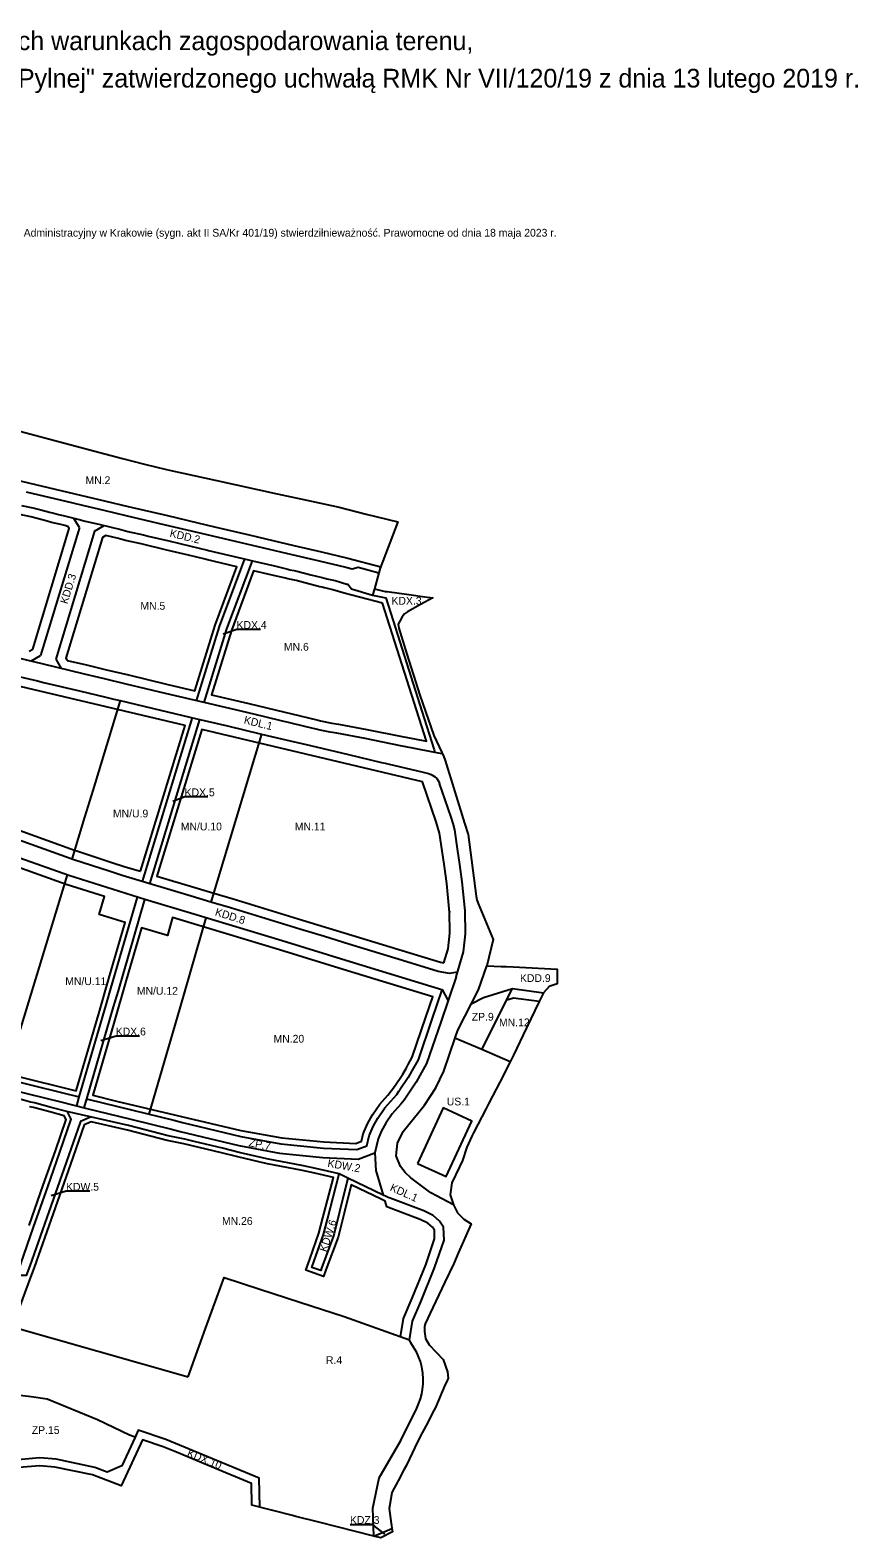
# Model space of a CAD drawing. Extents: x 7416945 to 7418410, y 5548550 to 5549803.
# Drawn here: x 7417879 to 7418410, y 5548834 to 5549803 of the extents above; entities that cross this region are included whole.
import ezdxf

# ---------------------------------------------------------------- set-up
doc = ezdxf.new("R2010")
doc.units = 0
for name, color, linetype in [('_LEGENDA_opisy', 7, 'Continuous'), ('info', 7, 'Continuous'), ('linie rozgraniczające', 7, 'Continuous'), ('nieprzekraczalna linia lokalizacyjna', 7, 'Continuous'), ('nieprzekraczalne linie zabudowy', 7, 'Continuous'), ('przeznaczenia terenów', 7, 'Continuous')]:
    doc.layers.add(name, color=color, linetype=linetype)

msp = doc.modelspace()

# ---------------------------------------------------------------- linework, layer by layer
at = {"layer": 'linie rozgraniczające'}
for p, q in [((7417910.44, 5549483.41), (7417907, 5549489.23)), ((7417920.17, 5549481.02), (7417926.47, 5549484.62)), ((7417879.25, 5549397.45), (7417885.56, 5549401.1)), ((7417895.3, 5549398.77), (7417898.72, 5549392.79)), ((7417983, 5549361.21), (7417950.85, 5549255.91)), ((7417955.64, 5549254.5), (7417987.87, 5549360.06)), ((7418027.45, 5549350.69), (7417994.99, 5549242.64)), ((7418166.75, 5549186.31), (7418172.2, 5549201.75)), ((7417864.45, 5548970.75), (7417980.26, 5548937.76)), ((7418099.66, 5548835.41), (7418111.24, 5548840.24))]:
    msp.add_line(p, q, dxfattribs=at)
for points in [[(7417852.72, 5549550.37), (7417888.31, 5549540.93), (7417919.44, 5549532.68), (7417938.2, 5549527.7), (7417952.33, 5549523.95), (7417966.49, 5549520.7), (7417974.19, 5549518.93), (7417977.16, 5549518.25), (7417997.67, 5549513.78), (7418037.57, 5549505.08), (7418059.54, 5549500.29), (7418077.3, 5549496.42), (7418094.56, 5549492.02), (7418115.04, 5549486.96), (7418103.65, 5549457.17), (7418102.86, 5549454.34), (7418099.94, 5549443.86), (7418106.76, 5549442.29), (7418108.19, 5549442.35), (7418122.08, 5549440.41), (7418132.41, 5549438.89), (7418137.43, 5549438.2), (7418129.53, 5549433.83), (7418121.11, 5549429.17), (7418119.23, 5549427.89), (7418117.76, 5549425.97), (7418116.34, 5549423.27), (7418115.31, 5549421.35), (7418115.6, 5549418.66), (7418120.86, 5549402.07), (7418129.05, 5549375.7), (7418138.08, 5549349.66), (7418143.16, 5549338.8), (7418144.48, 5549335.95), (7418145.33, 5549333.65), (7418157.85, 5549293.4), (7418160.08, 5549286.2), (7418165.24, 5549246.53), (7418165.65, 5549244.21), (7418166.54, 5549241.83), (7418176.19, 5549218.73), (7418172.2, 5549201.75), (7418181.31, 5549201.37), (7418184.59, 5549201.23), (7418188.99, 5549201.05), (7418193.18, 5549200.87), (7418217.35, 5549199.63), (7418217.35, 5549190.15), (7418212.24, 5549188.48), (7418208.51, 5549184.43), (7418205.86, 5549178.92), (7418197.7, 5549161.98), (7418189.26, 5549144.46), (7418187.12, 5549140.01), (7418180.41, 5549126.98), (7418173.46, 5549113.52), (7418171.71, 5549110.14), (7418163.61, 5549094.47), (7418162.61, 5549092.32), (7418159.41, 5549085.35), (7418156.56, 5549076.63), (7418154.61, 5549072.63), (7418149.59, 5549062.3), (7418148.63, 5549054.54), (7418150.76, 5549048.28), (7418153.26, 5549043.02), (7418155.63, 5549040.74), (7418157.33, 5549039.1), (7418162.18, 5549036.11), (7418153.74, 5549017.07), (7418150.87, 5549010.6), (7418145.13, 5548998.47), (7418137.43, 5548982.2), (7418132.54, 5548971.85), (7418132.07, 5548969.91), (7418132.17, 5548966.87), (7418132.84, 5548962.43), (7418135.11, 5548958.34), (7418144.07, 5548948.82), (7418146.86, 5548940.86), (7418147.22, 5548936.76), (7418146.17, 5548934.19), (7418145.34, 5548932.69), (7418139.2, 5548918.03), (7418138.18, 5548916.11), (7418133.15, 5548906.53), (7418129.42, 5548899.46), (7418125.91, 5548892.26), (7418122.47, 5548885.05), (7418120.34, 5548880.6), (7418118.9, 5548877.88), (7418115.17, 5548870.8), (7418111.44, 5548863.73), (7418111.16, 5548863.2), (7418109.38, 5548853.1), (7418110.78, 5548843.42), (7418110.93, 5548842.4), (7418111.24, 5548840.24), (7418111.54, 5548838.12), (7418104.13, 5548834.27), (7418099.66, 5548835.41), (7418064.28, 5548844.33), (7418049.5, 5548848.05), (7418047.4, 5548848.59), (7418021.32, 5548855.16), (7418020.96, 5548869.27), (7417996.77, 5548879.29), (7417972.83, 5548889.21), (7417964.24, 5548892.77), (7417950.97, 5548897.34), (7417937.39, 5548867.75), (7417918.95, 5548874.68), (7417894.76, 5548879.78), (7417885.14, 5548880.62), (7417871.53, 5548879.5)], [(7417876.37, 5549506.27), (7417906.25, 5549499.17), (7417913.36, 5549497.49), (7417926.18, 5549494.47), (7417940.37, 5549491.12), (7417965.6, 5549485.17), (7417985.07, 5549480.57), (7417995.92, 5549478.01), (7418025.11, 5549471.13), (7418046.9, 5549465.99), (7418064.57, 5549461.85), (7418081.51, 5549457.87), (7418085.64, 5549456.77), (7418089.45, 5549457.93), (7418096.58, 5549456.04), (7418102.86, 5549454.34)], [(7417873.31, 5549497.54), (7417880.65, 5549495.98), (7417885.75, 5549494.68), (7417891.36, 5549493.24), (7417894.12, 5549492.5), (7417897.08, 5549491.81), (7417900.04, 5549491.06), (7417902.59, 5549490.35), (7417910.27, 5549488.4), (7417914.28, 5549487.47), (7417923, 5549485.45), (7417937.11, 5549482.09), (7417941.65, 5549480.79), (7417951.57, 5549478.64), (7417954.72, 5549477.89), (7417967.95, 5549474.74), (7417982.01, 5549471.39), (7417992.77, 5549468.83), (7417993.33, 5549468.69), (7418019.03, 5549462.57), (7418021.57, 5549461.96), (7418035.79, 5549458.67), (7418044.26, 5549456.54), (7418045.73, 5549456.17), (7418048.39, 5549455.67), (7418051.05, 5549455.16), (7418059.2, 5549452.99), (7418066.39, 5549451.15), (7418067.82, 5549450.83), (7418069.05, 5549450.55), (7418069.39, 5549450.48), (7418074.82, 5549449.23), (7418082.22, 5549447.05), (7418082.82, 5549446.89), (7418085.29, 5549443.94), (7418098.8, 5549439.93)], [(7417910.44, 5549483.41), (7417885.56, 5549401.1)], [(7417920.17, 5549481.02), (7417895.3, 5549398.77)], [(7417985.69, 5549372.05), (7418000.49, 5549419.73), (7418016.67, 5549463.13)], [(7417990.57, 5549370.9), (7418005.27, 5549418.25), (7418021.57, 5549461.96)], [(7418099.94, 5549443.86), (7418098.79, 5549439.93), (7418107.3, 5549438.13), (7418113.47, 5549418.68), (7418130.38, 5549365.39), (7418138.25, 5549340.6), (7418138.78, 5549338.91)], [(7418143.54, 5549337.98), (7418138.78, 5549338.91), (7418124.65, 5549341.61), (7418116.66, 5549343.2), (7418094.03, 5549347.74), (7418075.82, 5549351.14), (7418071.5, 5549351.83), (7418064.08, 5549353.35), (7418062.54, 5549353.7), (7418056.13, 5549355.26), (7418044.71, 5549358.03), (7418041.02, 5549358.93), (7418029.5, 5549361.7), (7418017.97, 5549364.46), (7417990.57, 5549370.9), (7417965.81, 5549376.75), (7417940.53, 5549382.78), (7417926.59, 5549386.12), (7417913.74, 5549389.19), (7417886.55, 5549395.7), (7417866.12, 5549400.6)], [(7417863.34, 5549389.56), (7417883.55, 5549384.77), (7417887.45, 5549383.84), (7417910.58, 5549378.37), (7417927.56, 5549374.34), (7417932.66, 5549373.14), (7417936.56, 5549372.21), (7417962.55, 5549366.06), (7417985.92, 5549360.52), (7418005.58, 5549355.86), (7418027.45, 5549350.69), (7418040.18, 5549347.67), (7418058.98, 5549343.22), (7418083.3, 5549337.46), (7418104.51, 5549332.43), (7418106.94, 5549331.86), (7418109.37, 5549331.28), (7418130.35, 5549326.31), (7418134.6, 5549325.3), (7418136.33, 5549324.74), (7418138.47, 5549323.48), (7418139.96, 5549322.07), (7418141.08, 5549320.46), (7418141.82, 5549318.83)], [(7417936.56, 5549372.21), (7417919.01, 5549314.44), (7417913.77, 5549297.17), (7417905.62, 5549270.33)], [(7418147.34, 5549179.74), (7418143.99, 5549186.16), (7418084.45, 5549204.38), (7418040.68, 5549217.77), (7417983.92, 5549235), (7417952.55, 5549244.38), (7417903.8, 5549259.73), (7417872.26, 5549271.01), (7417847.4, 5549279.75), (7417826.56, 5549286.64), (7417807.47, 5549292.63), (7417790.03, 5549298.09), (7417775.67, 5549301.04), (7417764.12, 5549302.87), (7417752.53, 5549304.72), (7417740.93, 5549306.55), (7417719.26, 5549309.98), (7417700.5, 5549312.94), (7417681.74, 5549315.91), (7417662.97, 5549318.89), (7417638.22, 5549322.81), (7417619.42, 5549325.79), (7417605.57, 5549327.98), (7417599.85, 5549325.25)], [(7418158.2, 5549237.1), (7418156.32, 5549255.83), (7418154.78, 5549266.85), (7418153.36, 5549277.01), (7418151.66, 5549289.04), (7418150.46, 5549293.2), (7418149.25, 5549297.36), (7418143.54, 5549313.87), (7418141.82, 5549318.83)], [(7418153.3, 5549197.74), (7418148.24, 5549196.86), (7418140.97, 5549198.17), (7418118, 5549205.2), (7418083.6, 5549215.72), (7418067.82, 5549220.55), (7418052.04, 5549225.38), (7418007.55, 5549238.99), (7417994.99, 5549242.64), (7417982.32, 5549246.61), (7417938.04, 5549259.7), (7417929.5, 5549262.54), (7417918.16, 5549266.22), (7417906.81, 5549269.9), (7417851.87, 5549289.57)], [(7417902.54, 5549260.18), (7417862.8, 5549129.35)], [(7417927.67, 5549176.77), (7417930.69, 5549187.14), (7417947.78, 5549245.89)], [(7417932.49, 5549175.43), (7417935.5, 5549185.8), (7417952.55, 5549244.38)], [(7417955.29, 5549106.53), (7417974.92, 5549173.98), (7417991.96, 5549232.56)], [(7418152.41, 5549194.67), (7418157.08, 5549210.74), (7418158.49, 5549222.33), (7418158.2, 5549237.1)], [(7418152.41, 5549194.67), (7418142.52, 5549165.57), (7418133.47, 5549138.95), (7418129.18, 5549131.34), (7418126.73, 5549126.98), (7418119.13, 5549115.53), (7418116.87, 5549112.96), (7418111.41, 5549106.77), (7418107.29, 5549100.68), (7418104.48, 5549095.8), (7418102.31, 5549090.62), (7418100.12, 5549081.56), (7418100.83, 5549070.19), (7418105.64, 5549054.51)], [(7418150.76, 5549048.28), (7418136.18, 5549056), (7418129.36, 5549061.05), (7418123.42, 5549065.56), (7418119.69, 5549068.94), (7418116.62, 5549072.74), (7418113.94, 5549079.71), (7418114.77, 5549087.76), (7418118.34, 5549095.28), (7418132.16, 5549112.17), (7418139.43, 5549123.32), (7418144.47, 5549134.03), (7418151.74, 5549155.4), (7418153.47, 5549160.51), (7418166.75, 5549186.31)], [(7418143.26, 5549186.39), (7418136.84, 5549167.5), (7418127.97, 5549141.41), (7418123.95, 5549134.28), (7418121.61, 5549130.11), (7418116.27, 5549122.08)], [(7418162.18, 5549177.43), (7418170.05, 5549181.44), (7418188.69, 5549187.1), (7418208.51, 5549184.43)], [(7418168.94, 5549147.93), (7418188.69, 5549187.1)], [(7417908.75, 5549111.74), (7417910.43, 5549117.51), (7417927.67, 5549176.77)], [(7417913.6, 5549110.53), (7417915.28, 5549116.29), (7417932.49, 5549175.43)], [(7418187.12, 5549140.01), (7418168.94, 5549147.93), (7418151.71, 5549155.32)], [(7417791.78, 5549146.54), (7417835.03, 5549136.21), (7417879.03, 5549125.34), (7417899.92, 5549120.14), (7417910.43, 5549117.51)], [(7417788.92, 5549141.06), (7417833.61, 5549130.38), (7417877.58, 5549119.52), (7417898.47, 5549114.32), (7417914.41, 5549110.33), (7417943.45, 5549103.3), (7417969.7, 5549096.76), (7417975.19, 5549095.35), (7418012.94, 5549086.32), (7418038.97, 5549081.43), (7418066.78, 5549078.66), (7418089.62, 5549077.64), (7418100.12, 5549081.56)], [(7418054.47, 5549073.19), (7418030.76, 5549077.77), (7418012.99, 5549081.92), (7418002.38, 5549084.6), (7417984.13, 5549088.95), (7417978.23, 5549090.35), (7417967.59, 5549092.55), (7417941.97, 5549099.12), (7417902.4, 5549108.1), (7417892.31, 5549110.78), (7417881.65, 5549113.74), (7417879.1, 5549114.2), (7417874, 5549115.6), (7417870.28, 5549116.48), (7417838.19, 5549124.07), (7417797.73, 5549133.64), (7417799.37, 5549138.56)], [(7417915.28, 5549116.29), (7417915.84, 5549116.15), (7417944.88, 5549109.13), (7417971.17, 5549102.58), (7417976.63, 5549101.17), (7418014.19, 5549092.19), (7418039.82, 5549087.37), (7418067.21, 5549084.64), (7418088.67, 5549083.68), (7418095.04, 5549086.07), (7418096.59, 5549092.49), (7418099.09, 5549098.46), (7418102.19, 5549103.86), (7418106.66, 5549110.45), (7418114.36, 5549119.19), (7418115.67, 5549121.18), (7418116.27, 5549122.08)], [(7417917.65, 5549104.64), (7417911.1, 5549101.73), (7417901.89, 5549075.42), (7417890.76, 5549043.69), (7417878.59, 5549008.99), (7417876.3, 5549002.8), (7417870.46, 5549002.86), (7417870.18, 5549002.86), (7417872.8, 5549010.27), (7417881.05, 5549033.88), (7417890.12, 5549059.83), (7417897.87, 5549082.02), (7417905.29, 5549103.25), (7417902.77, 5549108.02)], [(7418099.66, 5548835.41), (7418099, 5548853.28), (7418102.92, 5548872.84), (7418116.82, 5548896.85), (7418127.14, 5548917.57), (7418128.12, 5548919.68), (7418129.56, 5548923.62), (7418130.4, 5548926.77), (7418130.92, 5548929.64), (7418131.29, 5548933.32), (7418131.33, 5548936.52), (7418131.06, 5548940.14), (7418130.38, 5548944.11), (7418129.45, 5548947.56), (7418128.57, 5548950.05), (7418127.11, 5548953.31), (7418125.11, 5548956.85), (7418123.26, 5548959.52), (7418122.53, 5548961.41), (7418124.44, 5548973.5), (7418129.7, 5548985.85), (7418138.59, 5549007.65), (7418144.65, 5549025.48), (7418144.39, 5549033.91), (7418141.8, 5549037.78), (7418137.7, 5549041.4), (7418131.79, 5549044.36), (7418110.17, 5549052.51), (7418108.77, 5549053.01), (7418107.14, 5549053.79), (7418105.64, 5549054.51), (7418082.98, 5549065.4), (7418077.39, 5549068.08), (7418062.36, 5549071.47), (7418054.47, 5549073.19)], [(7418082.98, 5549065.4), (7418077.56, 5549043.64), (7418074.1, 5549029.78), (7418073.75, 5549028.36), (7418066.01, 5549007.46), (7418065.48, 5549006.04), (7418059.82, 5549008.05), (7418061.32, 5549012.3), (7418067.22, 5549029.09), (7418069.81, 5549039.05), (7418077.39, 5549068.08)], [(7417980.26, 5548937.76), (7417991.5, 5548968.79), (7417998.82, 5548988.71), (7418003.49, 5549001.49), (7418026.31, 5548994.08), (7418051.99, 5548985.73), (7418080.46, 5548976.49), (7418122.53, 5548961.41)], [(7417946.22, 5548898.97), (7417942.6, 5548900.22), (7417922.04, 5548910.15), (7417889.72, 5548923.38), (7417879.42, 5548924.96), (7417863.45, 5548926.86), (7417853.47, 5548928.11)], [(7418026.35, 5548853.89), (7418025.88, 5548872.65), (7417965.92, 5548897.48), (7417948.32, 5548903.54), (7417946.22, 5548898.97), (7417937.72, 5548880.45), (7417928.22, 5548876.53), (7417920.35, 5548879.49), (7417895.5, 5548884.73), (7417885.15, 5548885.64), (7417870.98, 5548884.47)]]:
    msp.add_lwpolyline(points, dxfattribs=at)
at = {"layer": 'nieprzekraczalna linia lokalizacyjna'}
msp.add_lwpolyline([(7418127.69, 5549074.78), (7418146.13, 5549066.33), (7418162.52, 5549102.07), (7418144.07, 5549110.53), (7418127.69, 5549074.78)], dxfattribs=at)
at = {"layer": 'nieprzekraczalne linie zabudowy'}
for points in [[(7417662.42, 5549600.65), (7417653.36, 5549565.68), (7417721.79, 5549549.61), (7417728.3, 5549547.9), (7417750.79, 5549541.98), (7417808.77, 5549528.32), (7417826.2, 5549524.21), (7417842.21, 5549520.44), (7417877.75, 5549512.11), (7417907.63, 5549505.01), (7417914.74, 5549503.33), (7417927.56, 5549500.31), (7417941.75, 5549496.96), (7417966.98, 5549491.01), (7417986.45, 5549486.41), (7417997.3, 5549483.85), (7418019.43, 5549478.63), (7418030.21, 5549476.09), (7418048.27, 5549471.83), (7418065.94, 5549467.69), (7418082.97, 5549463.69), (7418104, 5549458.1)], [(7417878.32, 5549403.84), (7417880.5, 5549405.1), (7417903.93, 5549482.62), (7417903.1, 5549484.03), (7417901.05, 5549484.55), (7417898.5, 5549485.26), (7417895.66, 5549485.98), (7417892.66, 5549486.68), (7417889.84, 5549487.44), (7417884.26, 5549488.87), (7417879.28, 5549490.14), (7417872.12, 5549491.66)], [(7417902.64, 5549398.02), (7417915.14, 5549395.03), (7417927.99, 5549391.96), (7417941.93, 5549388.62), (7417967.2, 5549382.59), (7417984.55, 5549378.49), (7417997.65, 5549420.7), (7418011.62, 5549458.17), (7417991.91, 5549462.86), (7417991.35, 5549463), (7417980.62, 5549465.55), (7417966.56, 5549468.9), (7417950.24, 5549472.79), (7417940.19, 5549474.97), (7417935.59, 5549476.28), (7417927.39, 5549478.24), (7417925.22, 5549477), (7417901.79, 5549399.5), (7417902.64, 5549398.02)], [(7418105.25, 5549434.68), (7418080.6, 5549441.27), (7418073.3, 5549443.42), (7418068.11, 5549444.62), (7418067.79, 5549444.68), (7418066.5, 5549444.97), (7418064.98, 5549445.32), (7418057.68, 5549447.18), (7418049.72, 5549449.31), (7418044.44, 5549450.31), (7418042.8, 5549450.72), (7418034.38, 5549452.84), (7418022.4, 5549455.61), (7418008.11, 5549417.28), (7417995.28, 5549375.96), (7418019.36, 5549370.3), (7418042.43, 5549364.76), (7418046.13, 5549363.86), (7418063.92, 5549359.54), (7418065.36, 5549359.21), (7418072.58, 5549357.73), (7418076.84, 5549357.05), (7418095.17, 5549353.63), (7418117.84, 5549349.08), (7418125.8, 5549347.5), (7418133.37, 5549346.05), (7418105.25, 5549434.68)], [(7417949.72, 5549262.5), (7417978.32, 5549356.16), (7417837.8, 5549389.44), (7417835.66, 5549388.19), (7417831.71, 5549374.83), (7417825.61, 5549353.56), (7417819.8, 5549333.9), (7417812.9, 5549309.83), (7417813.51, 5549308.13), (7417835.59, 5549301.2), (7417853.81, 5549295.25), (7417907.36, 5549276.08), (7417908.75, 5549275.58), (7417931.37, 5549268.24), (7417939.84, 5549265.43), (7417949.72, 5549262.5)], [(7418144.6, 5549203.61), (7418147.26, 5549212.75), (7418148.48, 5549222.84), (7418148.2, 5549236.9), (7418148.25, 5549236.1), (7418146.39, 5549254.64), (7418144.88, 5549265.47), (7418143.46, 5549275.62), (7418141.86, 5549286.94), (7418139.72, 5549294.33), (7418130.82, 5549320.03), (7417989.04, 5549353.62), (7417960.27, 5549259.38), (7417984.07, 5549252.35), (7417996.72, 5549248.39), (7418009.26, 5549244.74), (7418053.8, 5549231.12), (7418085.36, 5549221.46), (7418142.39, 5549204.01), (7418144.6, 5549203.61)], [(7417799.6, 5549148.55), (7417830.66, 5549140.78), (7417908.42, 5549121.35), (7417923.1, 5549171.81), (7417929.47, 5549193.7), (7417939.89, 5549229.5), (7417923.27, 5549234.73), (7417926.71, 5549246.23), (7417901.89, 5549254.04), (7417870.25, 5549265.36), (7417861.19, 5549268.54), (7417858.1, 5549267.26), (7417830.16, 5549208.01), (7417825.59, 5549198.31), (7417799.6, 5549148.55)], [(7418014.27, 5549095.93), (7418040.39, 5549091.34), (7418067.5, 5549088.63), (7418088.03, 5549087.72), (7418091.65, 5549089.07), (7418092.78, 5549093.74), (7418095.5, 5549100.24), (7418098.8, 5549105.98), (7418103.49, 5549112.9), (7418108.53, 5549118.63), (7418112.94, 5549124.29), (7418118.19, 5549132.2), (7418120.47, 5549136.24), (7418120.99, 5549137.17), (7418121.64, 5549138.34), (7418124.3, 5549143.05), (7418133.05, 5549168.79), (7418137.5, 5549181.87), (7418082.69, 5549198.64), (7418038.93, 5549212.03), (7417982.18, 5549229.26), (7417970.27, 5549232.82), (7417966.97, 5549221.28), (7417950.4, 5549226.24), (7417940.61, 5549192.63), (7417933, 5549166.47), (7417919.1, 5549118.68), (7417934.38, 5549114.87), (7418014.27, 5549095.93)], [(7418205.78, 5549178.74), (7418189.18, 5549180.98), (7418184.96, 5549179.69)], [(7417878.22, 5549034.87), (7417887.29, 5549060.82), (7417895.04, 5549083.01), (7417902.03, 5549103), (7417900.74, 5549105.44), (7417891.52, 5549107.88), (7417880.98, 5549110.81), (7417878.44, 5549111.27)], [(7418116.78, 5548963.47), (7418118.63, 5548975.17), (7418124.16, 5548988.16), (7418132.97, 5549009.75), (7418138.62, 5549026.38), (7418138.45, 5549032.01), (7418137.24, 5549033.8), (7418134.32, 5549036.38), (7418129.38, 5549038.85), (7418117.91, 5549043.18), (7418107.97, 5549046.93), (7418106.84, 5549050.61), (7418104.34, 5549051.81), (7418085, 5549061.1), (7418080.47, 5549042.91), (7418077.01, 5549029.06), (7418076.62, 5549027.48), (7418068.82, 5549006.41), (7418067.26, 5549002.22), (7418055.99, 5549006.22), (7418058.49, 5549013.3), (7418064.35, 5549029.97), (7418066.91, 5549039.81), (7418073.7, 5549065.84), (7418061.71, 5549068.54), (7418053.87, 5549070.25), (7418030.14, 5549074.84), (7418012.28, 5549079), (7418001.67, 5549081.69), (7417977.58, 5549087.42), (7417966.91, 5549089.63), (7417941.27, 5549096.2), (7417917.96, 5549101.49), (7417913.51, 5549099.51), (7417904.72, 5549074.43), (7417893.59, 5549042.7), (7417881.41, 5549007.97), (7417879.11, 5549001.76), (7417867.35, 5548969.92)]]:
    msp.add_lwpolyline(points, dxfattribs=at)
at = {"layer": 'przeznaczenia terenów'}
for points in [[(7418026.74, 5549417.83), (7418011.56, 5549417.87), (7418002.92, 5549414.83)], [(7417993.03, 5549310.3), (7417978.1, 5549310.26), (7417970.44, 5549307.3)], [(7417949.16, 5549156.64), (7417934.04, 5549156.64), (7417924.34, 5549153.65)], [(7417917.2, 5549056.9), (7417902.08, 5549056.9), (7417892.39, 5549053.9)], [(7418084.44, 5548842.92), (7418098.58, 5548842.92), (7418106.39, 5548836.71)]]:
    msp.add_lwpolyline(points, dxfattribs=at)

# ---------------------------------------------------------------- texts
at = {"layer": '_LEGENDA_opisy'}
msp.add_text('Tereny dla których wyrokiem z dnia 12 września 2019 r. Wojewódzki Sąd Administracyjny w Krakowie (sygn. akt II SA/Kr 401/19) stwierdziłnieważność. Prawomocne od dnia 18 maja 2023 r.', height=5, dxfattribs=at).set_placement((7417656.59, 5549670.23))
at = {"layer": 'info'}
for s, p in [('Materiał pomocniczy zawierający linie rozgraniczające teren o różnym przeznaczeniu i różnych warunkach zagospodarowania terenu, ', (7417215.4, 5549790.04)), ('opracowane w skali 1:1000 pochodzące z Miejscowego Planu Zagospodarowania Przestrzennego obszaru "Rejon ulic Podłużnej i Pylnej" zatwierdzonego uchwałą RMK Nr VII/120/19 z dnia 13 lutego 2019 r.', (7416943.86, 5549766.04))]:
    msp.add_text(s, height=12, dxfattribs=at).set_placement(p)
at = {"layer": 'przeznaczenia terenów'}
for s, p in [('MN.2', (7417914.42, 5549511.27)), ('MN.5', (7417949.64, 5549430.53)), ('KDX.3', (7418110.93, 5549433.78)), ('KDX.4', (7418011.43, 5549418.25)), ('MN.6', (7418041.82, 5549404.22)), ('KDX.5', (7417978.07, 5549310.72)), ('MN/U.9', (7417932.04, 5549297.13)), ('MN/U.10', (7417975.62, 5549288.78)), ('MN.11', (7418048.82, 5549288.75)), ('MN/U.11', (7417901.4, 5549189.4)), ('KDD.9', (7418193.45, 5549191.39)), ('MN/U.12', (7417947.4, 5549183.21)), ('ZP.9', (7418162.48, 5549166.54)), ('MN.12', (7418179.98, 5549162.92)), ('KDX.6', (7417933.83, 5549157.06)), ('MN.20', (7418035.16, 5549152.42)), ('US.1', (7418146.43, 5549112.09)), ('KDW.5', (7417901.88, 5549057.31)), ('MN.26', (7418002.06, 5549035.34)), ('R.4', (7418068.84, 5548945.95)), ('ZP.15', (7417879.92, 5548901.01)), ('KDZ.3', (7418084.27, 5548843.24))]:
    msp.add_text(s, height=5, dxfattribs=at).set_placement(p)
for s, rotation, p in [('KDD.2', 346.60255, (7417968.17, 5549477.52)), ('KDD.3', 72.95172, (7417902.77, 5549433.87)), ('KDL.1', 346.19, (7418015.78, 5549357.56)), ('KDD.8', 342.65361, (7417997.22, 5549234.28)), ('ZP.7', 348.73953, (7418018.96, 5549085.94)), ('KDW.2', 350.10683, (7418069.58, 5549072.69)), ('KDL.1', 336.11399, (7418109.53, 5549057.51)), ('KDW.6', 71.64885, (7418069.2, 5549017.57)), ('KDX.10', 337.67501, (7417979.23, 5548886.87))]:
    msp.add_text(s, height=5, rotation=rotation, dxfattribs=at).set_placement(p)

doc.saveas('drawing.dxf')
